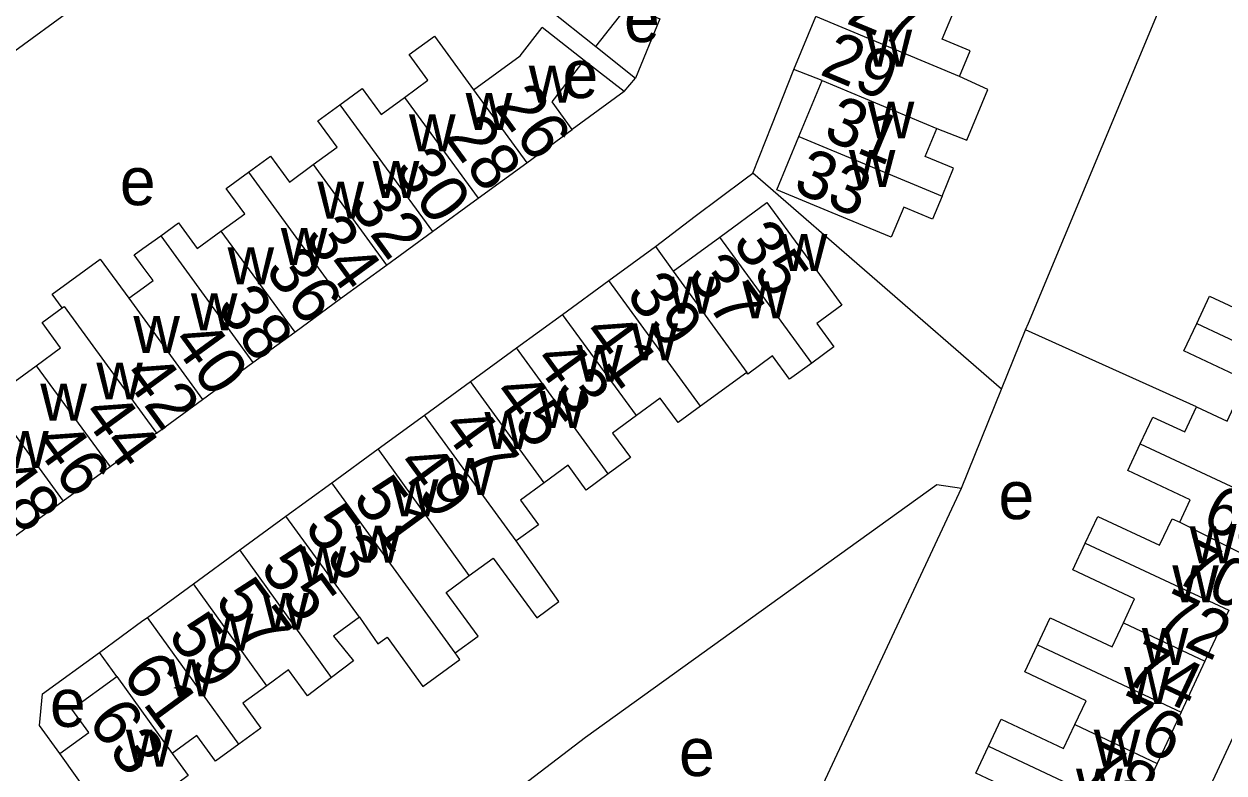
# Model space of a CAD drawing. Extents: x 159045 to 160918, y 380454 to 382516.
# Drawn here: x 159990.1 to 160089.8, y 381294.6 to 381356.9 of the extents above; entities that cross this region are included whole.
import ezdxf

# ---------------------------------------------------------------- set-up
doc = ezdxf.new("R2010")
doc.units = 0
for name, color, linetype in [('BLT_Basislijn', 7, 'Continuous'), ('BLT_Bebouwing', 7, 'Continuous'), ('BLT_Centroide', 7, 'Continuous'), ('BLT_Huisnummer', 7, 'Continuous'), ('BLT_Huisnummer_ tussenligend', 7, 'Continuous'), ('BLT_Onderverdeling_panden', 7, 'Continuous')]:
    doc.layers.add(name, color=color, linetype=linetype)

msp = doc.modelspace()

# ---------------------------------------------------------------- linework, layer by layer
at = {"layer": 'BLT_Basislijn'}
for p, q in [((159981.714, 381349.046), (160016.007, 381374.121)), ((160042.959, 381357.286), (160040.921, 381352.366)), ((160037.639, 381354.996), (160040.921, 381352.366)), ((160039.984, 381351.242), (160036.671, 381353.824)), ((160039.984, 381351.242), (160040.921, 381352.366)), ((160039.984, 381351.242), (160035.667, 381348.09)), ((160071.329, 381326.507), (160050.663, 381344.475)), ((160071.329, 381326.507), (160073.348, 381331.438)), ((160087.547, 381325.044), (160073.348, 381331.438)), ((160068.021, 381318.287), (160071.329, 381326.507)), ((160049.378, 381278.406), (160068.021, 381318.287))]:
    msp.add_line(p, q, dxfattribs=at)
for points in [[(160061.17, 381243.297), (160064.592, 381241.706), (160100.967, 381319.909), (160145.989, 381415.928)], [(160073.348, 381331.438), (160073.582, 381332.011), (160091.811, 381375.741)], [(160050.663, 381344.475), (160052.254, 381348.439), (160054.084, 381353.079)], [(160042.579, 381338.36), (160045.891, 381340.893), (160050.046, 381343.985), (160050.663, 381344.475)], [(160033.821, 381286.378), (160028.98, 381290.895), (160028.757, 381291.468), (160036.774, 381297.608), (160065.978, 381318.605), (160068.021, 381318.287)], [(159993.076, 381296.226), (159991.398, 381298.567), (159991.651, 381301.201), (159996.381, 381304.643)]]:
    msp.add_lwpolyline(points, dxfattribs=at)
at = {"layer": 'BLT_Bebouwing'}
for p, q in [((160054.084, 381353.079), (160055.909, 381357.469)), ((160036.671, 381353.824), (160033.164, 381356.557)), ((160056.432, 381352.154), (160054.084, 381353.079)), ((160054.496, 381347.496), (160056.432, 381352.154)), ((160031.888, 381345.331), (160035.667, 381348.09)), ((160027.848, 381342.381), (160031.888, 381345.331)), ((160024.056, 381339.612), (160027.848, 381342.381)), ((160020.237, 381336.824), (160024.056, 381339.612)), ((160044.062, 381336.328), (160047.934, 381339.154)), ((160038.706, 381335.533), (160042.579, 381338.36)), ((160042.579, 381338.36), (160044.062, 381336.328)), ((160016.418, 381334.036), (160020.237, 381336.824)), ((160034.864, 381332.729), (160038.706, 381335.533)), ((160012.605, 381331.252), (160016.418, 381334.036)), ((160031.036, 381329.935), (160034.864, 381332.729)), ((160009.135, 381328.718), (160012.605, 381331.252)), ((160027.211, 381327.144), (160031.036, 381329.935)), ((160004.957, 381325.667), (160009.135, 381328.718)), ((160023.388, 381324.353), (160027.211, 381327.144)), ((160001.121, 381322.867), (160004.957, 381325.667)), ((160087.547, 381325.044), (160090.104, 381323.862)), ((160019.543, 381321.547), (160023.388, 381324.353)), ((160015.7, 381318.742), (160019.543, 381321.547)), ((159997.26, 381320.047), (159993.379, 381317.213)), ((160011.88, 381315.954), (160015.7, 381318.742)), ((160008.039, 381313.151), (160011.88, 381315.954)), ((160004.196, 381310.346), (160008.039, 381313.151)), ((160000.365, 381307.55), (160004.196, 381310.346)), ((160090.227, 381308.137), (160088.249, 381303.912)), ((159997.838, 381302.647), (159996.381, 381304.643)), ((160088.249, 381303.912), (160086.264, 381299.67)), ((160086.264, 381299.67), (160084.274, 381295.419)), ((159998.551, 381288.656), (159993.076, 381296.226)), ((160084.274, 381295.419), (160082.299, 381291.201))]:
    msp.add_line(p, q, dxfattribs=at)
for points in [[(160032.195, 381359.288), (160033.713, 381358.092), (160037.639, 381354.996)], [(160037.639, 381354.996), (160040.309, 381358.383), (160042.959, 381357.286)], [(160067.851, 381352.503), (160068.731, 381354.619), (160066.408, 381355.585), (160067.343, 381357.834)], [(160027.467, 381351.387), (160031.335, 381354.211), (160033.164, 381356.557)], [(160021.732, 381350.755), (160023.683, 381352.18), (160022.128, 381354.309), (160024.219, 381355.836), (160027.467, 381351.387)], [(160035.667, 381348.09), (160033.991, 381350.384), (160036.671, 381353.824)], [(160065.973, 381348.187), (160068.449, 381347.192), (160070.205, 381351.417), (160067.851, 381352.503)], [(160016.367, 381350.146), (160018.206, 381351.488), (160019.781, 381349.33), (160021.732, 381350.755)], [(160014.145, 381345.171), (160016.126, 381346.617), (160014.529, 381348.804), (160016.367, 381350.146)], [(160066.399, 381342.548), (160065.608, 381340.646), (160063.212, 381341.642), (160062.171, 381339.137), (160057.281, 381341.17), (160052.664, 381343.089), (160054.496, 381347.496)], [(160066.399, 381342.548), (160067.365, 381344.872), (160065.003, 381345.854), (160065.973, 381348.187)], [(160008.756, 381344.535), (160010.594, 381345.876), (160012.164, 381343.725), (160014.145, 381345.171)], [(160006.477, 381339.646), (160008.455, 381341.09), (160006.919, 381343.194), (160008.756, 381344.535)], [(160047.934, 381339.154), (160051.849, 381342.011), (160054.796, 381337.972), (160058.069, 381333.488), (160055.996, 381331.975), (160057.418, 381330.026), (160055.575, 381328.681)], [(160001.472, 381339.264), (160002.944, 381340.334), (160004.5, 381338.203), (160006.477, 381339.646)], [(159998.827, 381334.065), (160000.004, 381334.924), (160000.839, 381335.534), (160000.018, 381336.658), (159999.28, 381337.669), (160000, 381338.195), (160001.472, 381339.264)], [(159993.284, 381333.274), (159992.454, 381334.413), (159996.447, 381337.327), (159998.827, 381334.065)], [(160087.563, 381331.972), (160088.629, 381334.249), (160093.815, 381331.821), (160094.652, 381333.61)], [(159991.121, 381328.454), (159993.158, 381329.942), (159991.615, 381332.056), (159993.284, 381333.274)], [(160090.104, 381323.862), (160091.672, 381327.273), (160086.497, 381329.696), (160087.563, 381331.972)], [(159985.682, 381327.756), (159987.525, 381329.101), (159989.084, 381326.967), (159991.121, 381328.454)], [(160055.575, 381328.681), (160053.733, 381327.337), (160052.323, 381329.27), (160050.263, 381327.767), (160050.169, 381327.896)], [(160050.169, 381327.896), (160046.326, 381325.091)], [(160046.326, 381325.091), (160044.472, 381323.738), (160042.99, 381325.769), (160041.004, 381324.319)], [(160082.865, 381321.977), (160083.906, 381324.2), (160086.568, 381322.954), (160087.547, 381325.044)], [(160041.004, 381324.319), (160039.018, 381322.869), (160040.512, 381320.821), (160038.669, 381319.476)], [(160001.121, 381322.867), (160000, 381322.048), (159997.26, 381320.047)], [(160086.156, 381315.448), (160087.031, 381317.317), (160081.825, 381319.755), (160082.865, 381321.977)], [(160038.669, 381319.476), (160036.826, 381318.131), (160035.327, 381320.185), (160033.347, 381318.739)], [(160033.347, 381318.739), (160031.367, 381317.294), (160032.862, 381315.245), (160031.017, 381313.899)], [(159993.379, 381317.213), (159989.358, 381314.277)], [(160078.298, 381313.721), (160079.34, 381315.946), (160084.483, 381313.538), (160085.517, 381315.747), (160086.156, 381315.448)], [(160027.112, 381311.031), (160029.091, 381312.475), (160032.714, 381307.513), (160034.566, 381308.865), (160031.017, 381313.899)], [(160081.469, 381307.087), (160082.405, 381309.085), (160077.257, 381311.496), (160078.298, 381313.721)], [(160025.935, 381304.592), (160027.839, 381305.982), (160025.182, 381309.622), (160027.112, 381311.031)], [(159996.381, 381304.643), (160000, 381307.284), (160000.365, 381307.55)], [(160017.996, 381307.572), (160015.839, 381305.998), (160017.485, 381303.937), (160015.675, 381302.549)], [(160017.996, 381307.572), (160019.512, 381305.341), (160020.281, 381305.902), (160023.265, 381301.815), (160026.329, 381304.052), (160025.935, 381304.592)], [(160074.326, 381305.261), (160075.377, 381307.504), (160080.534, 381305.089), (160081.469, 381307.087)], [(160077.442, 381298.638), (160078.379, 381300.627), (160073.276, 381303.018), (160074.326, 381305.261)], [(159993.076, 381296.226), (159995.499, 381297.994), (159994.096, 381299.916), (159997.838, 381302.647)], [(160015.675, 381302.549), (160013.68, 381301.019), (160012.097, 381303.188), (160010.293, 381301.872)], [(160010.293, 381301.872), (160008.293, 381300.412), (160009.8, 381298.347), (160007.968, 381297.01)], [(160070.26, 381296.837), (160071.311, 381299.081), (160076.505, 381296.65), (160077.442, 381298.638)], [(160007.968, 381297.01), (160006.027, 381295.593), (160004.471, 381297.726), (160002.421, 381296.23)], [(160073.457, 381290.168), (160074.393, 381292.167), (160069.21, 381294.593), (160070.26, 381296.837)], [(160002.421, 381296.23), (160003.758, 381294.399), (160001.277, 381292.587), (160002.202, 381291.321), (159999.993, 381289.708), (159998.551, 381288.656)]]:
    msp.add_lwpolyline(points, dxfattribs=at)
at = {"layer": 'BLT_Onderverdeling_panden'}
for p, q in [((160067.851, 381352.503), (160055.909, 381357.469)), ((160056.432, 381352.154), (160065.973, 381348.187)), ((160021.732, 381350.755), (160027.848, 381342.381)), ((160027.467, 381351.387), (160031.888, 381345.331)), ((160016.367, 381350.146), (160024.056, 381339.612)), ((160054.496, 381347.496), (160066.399, 381342.548)), ((160008.756, 381344.535), (160016.418, 381334.036)), ((160014.145, 381345.171), (160020.237, 381336.824)), ((160006.477, 381339.646), (160012.605, 381331.252)), ((160001.472, 381339.264), (160009.135, 381328.718)), ((160055.575, 381328.681), (160047.934, 381339.154)), ((160046.326, 381325.091), (160038.706, 381335.533)), ((160044.062, 381336.328), (160050.169, 381327.896)), ((159998.827, 381334.065), (160004.957, 381325.667)), ((160041.004, 381324.319), (160034.864, 381332.729)), ((160087.563, 381331.972), (160099.539, 381326.364)), ((160038.669, 381319.476), (160031.036, 381329.935)), ((159985.682, 381327.756), (159993.379, 381317.213)), ((159991.121, 381328.454), (159997.26, 381320.047)), ((160033.347, 381318.739), (160027.211, 381327.144)), ((160031.017, 381313.899), (160023.388, 381324.353)), ((160027.112, 381311.031), (160019.543, 381321.547)), ((160082.865, 381321.977), (160094.849, 381316.367)), ((160025.935, 381304.592), (160015.7, 381318.742)), ((160017.996, 381307.572), (160011.88, 381315.954)), ((160086.156, 381315.448), (160092.22, 381312.394)), ((160078.298, 381313.721), (160090.227, 381308.137)), ((160015.675, 381302.549), (160008.039, 381313.151)), ((160010.293, 381301.872), (160004.196, 381310.346)), ((160007.968, 381297.01), (160000.365, 381307.55)), ((160081.469, 381307.087), (160088.249, 381303.912)), ((160074.326, 381305.261), (160086.264, 381299.67)), ((159997.838, 381302.647), (160002.421, 381296.23)), ((160077.442, 381298.638), (160084.274, 381295.419)), ((160070.26, 381296.837), (160082.299, 381291.201))]:
    msp.add_line(p, q, dxfattribs=at)
msp.add_lwpolyline([(159993.284, 381333.274), (159993.44, 381333.388), (160001.121, 381322.867)], dxfattribs=at)

# ---------------------------------------------------------------- texts
at = {"layer": 'BLT_Centroide'}
for s, p in [('e', (160039.972, 381355.358)), ('w', (160060.047, 381353.312)), ('e', (160034.857, 381350.701)), ('w', (160032.062, 381350.312)), ('w', (160026.812, 381348.047)), ('w', (160060.234, 381347.344)), ('w', (160022.109, 381346.266)), ('w', (160019.094, 381342.391)), ('w', (160058.656, 381343.312)), ('e', (159998.076, 381341.802)), ('w', (160014.5, 381340.672)), ('w', (160011.453, 381336.844)), ('w', (160053, 381336.328)), ('w', (160007.031, 381335.234)), ('w', (160043.672, 381332.797)), ('w', (160003.984, 381331.406)), ('w', (160049.812, 381332.391)), ('w', (159999.203, 381329.531)), ('w', (160040.594, 381328.906)), ('w', (160036.016, 381327.125)), ('w', (159996.125, 381325.656)), ('w', (159991.469, 381323.891)), ('w', (160032.938, 381323.297)), ('w', (160028.375, 381321.547)), ('w', (159988.297, 381319.953)), ('w', (160025.281, 381317.719)), ('w', (160020.688, 381315.938)), ('e', (160071.088, 381315.713)), ('w', (160017.609, 381312.109)), ('w', (160086.977, 381312.031)), ('w', (160013.016, 381310.375)), ('w', (160085.531, 381308.812)), ('w', (160009.938, 381306.516)), ('w', (160005.312, 381304.797)), ('w', (160083, 381303.594)), ('w', (160002.109, 381301)), ('w', (160081.539, 381300.344)), ('e', (159992.265, 381298.452)), ('w', (159998.578, 381295.156)), ('w', (160079.008, 381295.156)), ('e', (160044.538, 381294.367)), ('w', (160077.539, 381291.906))]:
    msp.add_text(s, height=4, dxfattribs=at).set_placement(p)
at = {"layer": 'BLT_Huisnummer'}
for s, rotation, p in [('29', 337.43074, (160056.13, 381352.696)), ('26', 306.13019, (160029.065, 381350.028)), ('30', 306.12358, (160020.752, 381344.757)), ('33', 337.4243, (160053.892, 381343.003)), ('34', 306.13114, (160013.291, 381339.149)), ('35', 305.1414, (160048.889, 381338.713)), ('39', 306.13256, (160040.048, 381334.408)), ('38', 306.12704, (160006.016, 381333.34)), ('43', 306.12205, (160032.36, 381328.868)), ('42', 306.14109, (159998.227, 381327.658)), ('47', 306.12607, (160024.711, 381323.319)), ('46', 306.13161, (159990.768, 381322.017)), ('51', 306.11669, (160017.337, 381317.433)), ('55', 306.12202, (160009.636, 381311.659)), ('70', 334.90682, (160085.565, 381310.578)), ('59', 306.32218, (160001.977, 381306.055)), ('74', 334.9046, (160081.344, 381302.239)), ('63', 306.11791, (159995.314, 381298.919)), ('78', 334.77182, (160077.603, 381293.782))]:
    msp.add_text(s, height=4, rotation=rotation, dxfattribs=at).set_placement(p)
at = {"layer": 'BLT_Huisnummer_ tussenligend'}
for s, rotation, p in [('27', 337.42719, (160058.325, 381356.949)), ('31', 337.43074, (160056.407, 381347.376)), ('28', 306.13019, (160024.978, 381347.464)), ('32', 306.12358, (160017.01, 381341.844)), ('36', 306.13114, (160010.052, 381336.418)), ('37', 305.1414, (160045.13, 381335.995)), ('41', 306.13256, (160036.396, 381331.138)), ('40', 306.12704, (160002.262, 381330.447)), ('45', 306.12205, (160028.95, 381326.139)), ('44', 306.14109, (159994.809, 381324.428)), ('49', 306.12607, (160020.965, 381320.241)), ('48', 306.13161, (159986.681, 381319.112)), ('68', 334.91457, (160087.806, 381315.17)), ('53', 306.11669, (160013.322, 381315.067)), ('57', 306.12202, (160005.877, 381308.941)), ('72', 334.90682, (160083.722, 381306.429)), ('61', 306.32218, (159998.156, 381302.787)), ('76', 334.9046, (160079.918, 381297.953))]:
    msp.add_text(s, height=4, rotation=rotation, dxfattribs=at).set_placement(p)

doc.saveas('drawing.dxf')
